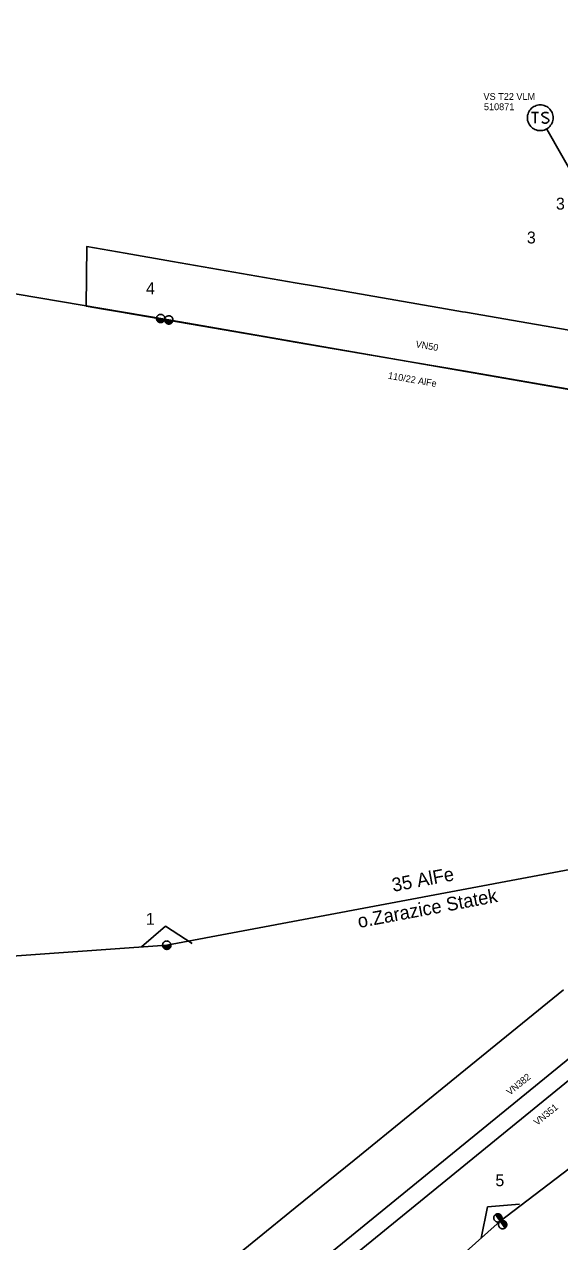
# Model space of a CAD drawing. Extents: x -545588 to -543214, y -1196037 to -1194452.
# Drawn here: x -545402.3 to -545323.7, y -1195024.5 to -1194845.7 of the extents above; entities that cross this region are included whole.
import ezdxf

# ---------------------------------------------------------------- set-up
doc = ezdxf.new("R2010")
doc.units = 0
for name, color, linetype in [('Vrstva 1', 7, 'Continuous'), ('Vrstva 12', 7, 'Continuous'), ('Vrstva 13', 7, 'Continuous'), ('Vrstva 14', 7, 'Continuous'), ('Vrstva 15', 7, 'Continuous'), ('Vrstva 18', 7, 'Continuous'), ('Vrstva 2', 7, 'Continuous'), ('Vrstva 25', 7, 'Continuous'), ('Vrstva 26', 7, 'Continuous'), ('Vrstva 27', 7, 'Continuous'), ('Vrstva 3', 7, 'Continuous'), ('Vrstva 35', 7, 'Continuous'), ('Vrstva 52', 7, 'Continuous'), ('Vrstva 53', 7, 'Continuous'), ('Vrstva 54', 7, 'Continuous'), ('Vrstva 6', 7, 'Continuous')]:
    doc.layers.add(name, color=color, linetype=linetype)

# ---------------------------------------------------------------- blocks, each defined once
blk = doc.blocks.new('VN860')
at = {"layer": 'Vrstva 15'}
for points in [[(-3.74, 0), (0.01, 2.82)], [(0.01, 2.82), (3.76, 0)]]:
    blk.add_lwpolyline(points, dxfattribs=at)
blk = doc.blocks.new('VN440')
at = {"layer": 'Vrstva 2'}
for points in [[(1.22, 0), (1.21, 0.13), (1.19, 0.25), (1.16, 0.38), (1.11, 0.5), (1.05, 0.61), (0.98, 0.72), (0.9, 0.82), (0.81, 0.91), (0.71, 0.99), (0.6, 1.06), (0.49, 1.12), (0.37, 1.16), (0.25, 1.2), (0.12, 1.22), (-0.01, 1.22), (-0.14, 1.22), (-0.26, 1.2), (-0.39, 1.16), (-0.51, 1.12), (-0.62, 1.06), (-0.73, 0.99), (-0.83, 0.91), (-0.92, 0.82), (-1, 0.72), (-1.07, 0.61), (-1.13, 0.5), (-1.18, 0.38), (-1.21, 0.25), (-1.23, 0.13), (-1.24, 0), (-1.23, -0.13), (-1.21, -0.26), (-1.18, -0.38), (-1.13, -0.5), (-1.07, -0.62), (-1, -0.73), (-0.92, -0.83), (-0.83, -0.92), (-0.73, -1), (-0.62, -1.07), (-0.51, -1.13), (-0.39, -1.17), (-0.26, -1.2), (-0.14, -1.23), (-0.01, -1.23), (0.12, -1.23), (0.25, -1.2), (0.37, -1.17), (0.49, -1.13), (0.6, -1.07), (0.71, -1), (0.81, -0.92), (0.9, -0.83), (0.98, -0.73), (1.05, -0.62), (1.11, -0.5), (1.16, -0.38), (1.19, -0.26), (1.21, -0.13), (1.22, 0)], [(-1.24, 0), (1.22, 0)], [(-1.18, -0.34), (1.1, -0.34)], [(-1.01, -0.63), (0.97, -0.63)], [(-0.74, -0.92), (0.68, -0.92)]]:
    blk.add_lwpolyline(points, dxfattribs=at)
blk = doc.blocks.new('VN610')
at = {"layer": 'Vrstva 6'}
for points in [[(1.88, 0), (1.87, 0.2), (1.84, 0.39), (1.79, 0.58), (1.72, 0.77), (1.63, 0.94), (1.52, 1.11), (1.4, 1.26), (1.26, 1.4), (1.1, 1.53), (0.94, 1.63), (0.76, 1.72), (0.58, 1.8), (0.39, 1.85), (0.19, 1.88), (-0.01, 1.89), (-0.21, 1.88), (-0.4, 1.85), (-0.59, 1.8), (-0.78, 1.72), (-0.95, 1.63), (-1.12, 1.53), (-1.27, 1.4), (-1.41, 1.26), (-1.54, 1.11), (-1.64, 0.94), (-1.73, 0.77), (-1.8, 0.58), (-1.86, 0.39), (-1.89, 0.2), (-1.9, 0), (-1.89, -0.2), (-1.86, -0.39), (-1.8, -0.58), (-1.73, -0.77), (-1.64, -0.95), (-1.54, -1.11), (-1.41, -1.27), (-1.27, -1.41), (-1.12, -1.53), (-0.95, -1.64), (-0.78, -1.73), (-0.59, -1.8), (-0.4, -1.85), (-0.21, -1.88), (-0.01, -1.89), (0.19, -1.88), (0.39, -1.85), (0.58, -1.8), (0.76, -1.73), (0.94, -1.64), (1.1, -1.53), (1.26, -1.41), (1.4, -1.27), (1.52, -1.11), (1.63, -0.95), (1.72, -0.77), (1.79, -0.58), (1.84, -0.39), (1.87, -0.2), (1.88, 0)], [(-1.27, 0.78), (-0.26, 0.78)], [(-0.76, 0.78), (-0.76, -0.79)], [(1.19, 0.66), (0.94, 0.78), (0.62, 0.78), (0.37, 0.66), (0.24, 0.47), (0.24, 0.4), (0.37, 0.22), (1.12, -0.16), (1.25, -0.32), (1.25, -0.48), (1.12, -0.67), (0.87, -0.79), (0.62, -0.79), (0.49, -0.73), (0.24, -0.6)]]:
    blk.add_lwpolyline(points, dxfattribs=at)
blk = doc.blocks.new('VN450')
at = {"layer": 'Vrstva 2'}
for points in [[(0, 0), (-0.01, 0.13), (-0.03, 0.25), (-0.06, 0.38), (-0.11, 0.5), (-0.16, 0.61), (-0.23, 0.72), (-0.31, 0.82), (-0.4, 0.91), (-0.5, 0.99), (-0.61, 1.06), (-0.72, 1.11), (-0.84, 1.16), (-0.97, 1.19), (-1.09, 1.21), (-1.22, 1.22), (-1.35, 1.21), (-1.47, 1.19), (-1.59, 1.16), (-1.71, 1.11), (-1.83, 1.06), (-1.93, 0.99), (-2.03, 0.91), (-2.12, 0.82), (-2.2, 0.72), (-2.27, 0.61), (-2.33, 0.5), (-2.38, 0.38), (-2.41, 0.25), (-2.43, 0.13), (-2.44, 0), (-2.43, -0.13), (-2.41, -0.25), (-2.38, -0.38), (-2.33, -0.5), (-2.27, -0.61), (-2.2, -0.72), (-2.12, -0.82), (-2.03, -0.91), (-1.93, -0.99), (-1.83, -1.06), (-1.71, -1.11), (-1.59, -1.16), (-1.47, -1.19), (-1.35, -1.21), (-1.22, -1.22), (-1.09, -1.21), (-0.97, -1.19), (-0.84, -1.16), (-0.72, -1.11), (-0.61, -1.06), (-0.5, -0.99), (-0.4, -0.91), (-0.31, -0.82), (-0.23, -0.72), (-0.16, -0.61), (-0.11, -0.5), (-0.06, -0.38), (-0.03, -0.25), (-0.01, -0.13), (0, 0)], [(-2.44, 0), (2.44, 0)], [(2.44, 0), (2.43, 0.13), (2.41, 0.25), (2.38, 0.38), (2.33, 0.5), (2.27, 0.61), (2.2, 0.72), (2.12, 0.82), (2.03, 0.91), (1.94, 0.99), (1.83, 1.06), (1.71, 1.11), (1.6, 1.16), (1.47, 1.19), (1.35, 1.21), (1.22, 1.22), (1.09, 1.21), (0.97, 1.19), (0.84, 1.16), (0.72, 1.11), (0.61, 1.06), (0.5, 0.99), (0.4, 0.91), (0.31, 0.82), (0.23, 0.72), (0.16, 0.61), (0.11, 0.5), (0.06, 0.38), (0.03, 0.25), (0.01, 0.13), (0, 0), (0.01, -0.13), (0.03, -0.25), (0.06, -0.38), (0.11, -0.5), (0.16, -0.61), (0.23, -0.72), (0.31, -0.82), (0.4, -0.91), (0.5, -0.99), (0.61, -1.06), (0.72, -1.11), (0.84, -1.16), (0.97, -1.19), (1.09, -1.21), (1.22, -1.22), (1.35, -1.21), (1.47, -1.19), (1.6, -1.16), (1.71, -1.11), (1.83, -1.06), (1.94, -0.99), (2.03, -0.91), (2.12, -0.82), (2.2, -0.72), (2.27, -0.61), (2.33, -0.5), (2.38, -0.38), (2.41, -0.25), (2.43, -0.13), (2.44, 0)], [(-2.4, -0.31), (-0.04, -0.31)], [(-2.26, -0.61), (-0.17, -0.61)], [(-2.01, -0.92), (-0.42, -0.92)], [(0.04, -0.31), (2.4, -0.31)], [(0.17, -0.61), (2.27, -0.61)], [(0.42, -0.92), (2.02, -0.92)]]:
    blk.add_lwpolyline(points, dxfattribs=at)

msp = doc.modelspace()

# ---------------------------------------------------------------- linework, layer by layer
at = {"layer": 'Vrstva 1'}
for points in [[(-545292.23, -1194904.36), (-545301.79, -1194902.92), (-545381.67, -1194889.04), (-545464.66, -1194874.97), (-545546.4, -1194860.3), (-545587.31, -1194845.75)], [(-545395.75, -1195077.92), (-545332.4, -1195021.48), (-545278.54, -1194980.38), (-545246.31, -1194956.61)], [(-545290.64, -1194971.78), (-545405.11, -1195065.07), (-545495.54, -1195139.14), (-545571.44, -1195160.65)], [(-545289.27, -1194973.82), (-545403.67, -1195067.08), (-545494.32, -1195141.28), (-545571.32, -1195163.18)]]:
    msp.add_lwpolyline(points, dxfattribs=at)
at = {"layer": 'Vrstva 35'}
for points in [[(-545312.5, -1194900.99), (-545324.01, -1194899.01), (-545337.5, -1194896.69), (-545345.34, -1194895.34), (-545362.5, -1194892.39), (-545366.67, -1194891.67), (-545387.5, -1194888.09), (-545388.01, -1194888.01), (-545390.95, -1194887.5), (-545393.22, -1194887.11), (-545393.11, -1194878.37), (-545387.5, -1194879.34), (-545380.55, -1194880.55), (-545362.5, -1194883.68), (-545359.24, -1194884.24), (-545340.46, -1194887.5), (-545337.94, -1194887.94), (-545337.5, -1194888.01), (-545316.63, -1194891.63)], [(-545384.64, -1195037.5), (-545362.5, -1195019.51), (-545353.87, -1195012.5), (-545337.5, -1194999.2), (-545323.09, -1194987.5)]]:
    msp.add_lwpolyline(points, dxfattribs=at)
at = {"layer": 'Vrstva 52'}
for points in [[(-545318.54, -1194873.42), (-545325.57, -1194861.13)], [(-545295.62, -1194964.82), (-545381.37, -1194980.94), (-545453.74, -1194986.07), (-545493.42, -1194989.16)]]:
    msp.add_lwpolyline(points, dxfattribs=at)

# ---------------------------------------------------------------- block references
at = {"layer": 'Vrstva 13'}
for name, p, xscale, yscale, rotation in [('VN450', (-545381.67, -1194889.04), 0.5, 0.5, -9.622102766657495), ('VN440', (-545381.37, -1194980.94), 0.5, 0.5000000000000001, 4.054341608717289), ('VN450', (-545332.4, -1195021.48), 0.49999999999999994, 0.5000000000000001, 125.22301664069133)]:
    msp.add_blockref(name, p, dxfattribs=dict(at, xscale=xscale, yscale=yscale, rotation=rotation))
at = {"layer": 'Vrstva 18'}
for p, rotation in [((-545381.37, -1194980.94), 4.054836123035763), ((-545332.4, -1195021.48), 41.696461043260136)]:
    msp.add_blockref('VN860', p, dxfattribs=dict(at, rotation=rotation))
at = {"layer": 'Vrstva 25', "rotation": -0.058288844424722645}
msp.add_blockref('VN610', (-545326.52, -1194859.46), dxfattribs=at)

# ---------------------------------------------------------------- texts
at = {"layer": 'Vrstva 12'}
msp.add_text('3', height=1.75, dxfattribs=at).set_placement((-545328.49, -1194877.92))
at = {"layer": 'Vrstva 14'}
for s, p in [('3', (-545324.22, -1194872.95)), ('4', (-545384.42, -1194885.38)), ('1', (-545384.44, -1194977.95)), ('5', (-545333.11, -1195016.33))]:
    msp.add_text(s, height=1.75, dxfattribs=at).set_placement(p)
at = {"layer": 'Vrstva 2'}
msp.add_text('110/22 AlFe', height=1, rotation=350.143, dxfattribs=at).set_placement((-545348.93, -1194897.77))
at = {"layer": 'Vrstva 26'}
msp.add_text('510871', height=1, dxfattribs=at).set_placement((-545334.8, -1194858.35))
at = {"layer": 'Vrstva 27'}
msp.add_text('VS T22 VLM', height=1, dxfattribs=at).set_placement((-545334.86, -1194856.84))
at = {"layer": 'Vrstva 3'}
for s, rotation, p in [('VN50', 350.143, (-545344.88, -1194893.15)), ('VN382', 39.181, (-545330.99, -1195003.04)), ('VN351', 39.19, (-545326.98, -1195007.49))]:
    msp.add_text(s, height=1, rotation=rotation, dxfattribs=at).set_placement(p)
at = {"layer": 'Vrstva 53'}
msp.add_text('35 AlFe', height=2, rotation=10.647, dxfattribs=at).set_placement((-545348.12, -1194973.12))
at = {"layer": 'Vrstva 54'}
msp.add_text('o.Zarazice Statek', height=2, rotation=10.647, dxfattribs=at).set_placement((-545353.15, -1194978.43))

doc.saveas('drawing.dxf')
